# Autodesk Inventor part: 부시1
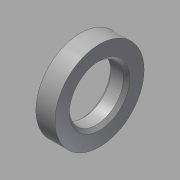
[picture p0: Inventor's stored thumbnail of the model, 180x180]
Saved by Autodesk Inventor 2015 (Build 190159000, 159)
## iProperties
Created: 2015-09
Part Number: 부시1
Material: 강철, 연강
Document SubType Name: Modeling
Designer: mduedu
Density: 7.86 g/cm^3
Description: 외주 가공
Mass: 17.8983 g
Surface Area: 15.6581 cm^2
Volume: 2.27713 cm^3
Appearance: 강철
Author: mduedu
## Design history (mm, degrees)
sketch "스케치1"
  geometry: C1 r 14 at (0, 0); C2 r 8.5 at (0, 0); 1 further point
  constraints: 2 centre point, 2 coincident
  dimensions: "d0" = 28 diameter of C1; "d2" = 17 diameter of C2
extrude "돌출1" new body sketch "스케치1" distance "d3" = 6; taper "d4" = 0 deg
chamfer "모따기1" distance "d5" = 1; stored, may be unused: second distance "d6" = 2, angle "d7" = 45 deg
node "솔리드1"
